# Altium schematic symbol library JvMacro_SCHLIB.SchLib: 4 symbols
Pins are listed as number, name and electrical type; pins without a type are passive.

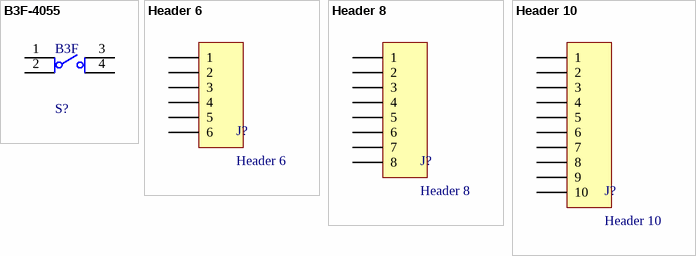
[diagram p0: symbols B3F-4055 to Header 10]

## B3F-4055
designator S?, comment B3F
B3F pushbutton, 12x12mm, through hole
footprint Omron_B3F-4055
pins: 1, 2, 3, 4

## Header 6
designator J?
2,54mm pitch header, 6 positions; Pitch: 2.54mm
footprint HDR1X6 (Connector; Header; 6 Position; Vertical)
pins: 1, 2, 3, 4, 5, 6

## Header 8
designator J?
2,54mm pitch header, 8 positions; Pitch: 2.54mm
footprint HDR1X8 (Connector; Header; 8 Position; Vertical)
pins: 1, 2, 3, 4, 5, 6, 7, 8

## Header 10
designator J?
2,54mm pitch header, 10 positions; Pitch: 2.54mm
footprint HDR1X10 (Connector; Header; 10 Position; Vertical)
pins: 1, 2, 3, 4, 5, 6, 7, 8, 9, 10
